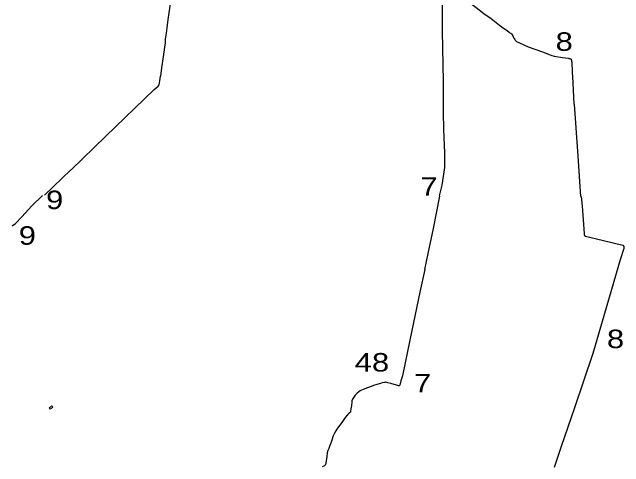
# Model space of a CAD drawing. Extents: x 476989 to 498418, y 4381813 to 4416555.
# Drawn here: x 485779 to 487432, y 4383399 to 4384627 of the extents above; entities that cross this region are included whole.
import ezdxf
from ezdxf.enums import TextEntityAlignment as Align

# ---------------------------------------------------------------- set-up
doc = ezdxf.new("R2010")
doc.units = 0
doc.header["$LTSCALE"] = 20
doc.linetypes.add('MEDIUM_DASHED', pattern=[4.5, 3, -1.5])
for name, color, linetype, lineweight in [('13', 7, 'Continuous', 13), ('48', 7, 'MEDIUM_DASHED', 13), ('6', 7, 'Continuous', 25)]:
    doc.layers.add(name, color=color, linetype=linetype, lineweight=lineweight)

msp = doc.modelspace()

# ---------------------------------------------------------------- linework, layer by layer
at = {"layer": '48'}
msp.add_lwpolyline([(485881.83, 4383554.31), (485889.05, 4383559.53), (485886.53, 4383563.02), (485879.31, 4383557.8)], close=True, dxfattribs=at)
at = {"layer": '6'}
for p, q in [((487294.23, 4384435.36), (487297.15, 4384378.58)), ((485866.75, 4384132.44), (485938.06, 4384200.82)), ((486902.72, 4383974.83), (486893.73, 4383931.56))]:
    msp.add_line(p, q, dxfattribs=at)
for points in [[(486218.38, 4384758.97), (486215.66, 4384730.87), (486211.01, 4384695.06), (486207.54, 4384662.09), (486202.36, 4384625.46), (486200.14, 4384606.58), (486197.13, 4384584.8), (486195.49, 4384569.88), (486192.94, 4384553.94), (486192.12, 4384543.7), (486190.9, 4384532.35), (486188.75, 4384518.64), (486187.3, 4384506.44), (486183.04, 4384476.01), (486180.3, 4384454.17)], [(486945.56, 4384310.48), (486944.94, 4384355.68), (486944.63, 4384415.82), (486944.32, 4384439.71), (486942.16, 4384575.23), (486941.95, 4384690.43)], [(486942.08, 4384690.84), (486954.99, 4384685.27), (486964.75, 4384681.01), (486968.71, 4384679.29), (486972.07, 4384677.74), (486975.6, 4384676.25), (486980.04, 4384673.88), (486984.28, 4384670.81), (486999.05, 4384662.28), (487012.48, 4384653.89), (487024.7, 4384645.52), (487041.38, 4384633.38), (487053.31, 4384623.24), (487073.79, 4384609.31), (487096.07, 4384592.1), (487101.96, 4384587.52)], [(487101.8, 4384587.52), (487116.55, 4384577.26), (487122.3, 4384573.1), (487124.64, 4384571.25), (487125.02, 4384570.92), (487125.52, 4384570.61), (487127.05, 4384569.38), (487128.24, 4384568.15), (487130.32, 4384565.69), (487131.92, 4384562.86), (487133.39, 4384560.05), (487135.2, 4384556.68), (487136.02, 4384555.28), (487137.14, 4384552.89), (487137.22, 4384552.72), (487138.44, 4384551.25), (487140.08, 4384549.42), (487141.78, 4384547.95), (487149.75, 4384543.71), (487173.68, 4384533.05), (487212.25, 4384519.67), (487233.09, 4384511.72), (487237.67, 4384509.96), (487243.84, 4384508.31), (487266.13, 4384504.33), (487282.11, 4384502.38), (487283.68, 4384502.03), (487285.79, 4384501.45), (487287.55, 4384500.79), (487289.12, 4384499.93), (487290.33, 4384497.55), (487290.92, 4384494.24), (487291.11, 4384491.51), (487292.47, 4384465.24), (487294.23, 4384435.67)], [(485938.1, 4384200.87), (486031.09, 4384290.93), (486163.16, 4384417.62), (486173.25, 4384426.84), (486175.9, 4384430.9), (486178.46, 4384441.13), (486180.3, 4384454.17)], [(487297.44, 4384378.01), (487307.43, 4384237.38), (487314.66, 4384129.23)], [(486934.14, 4384130.55), (486940.93, 4384159.51), (486948.64, 4384207.59), (486948.03, 4384246.42), (486946.18, 4384288.58), (486945.56, 4384310.48)], [(485779.25, 4384049.24), (485787.67, 4384056.24), (485804.97, 4384074.17), (485831.97, 4384103.43), (485861.35, 4384131.61)], [(486934.14, 4384129.53), (486916.73, 4384042.26), (486902.62, 4383974.52)], [(487317.13, 4384128.79), (487319.18, 4384102.5), (487324.43, 4384028.76), (487324.46, 4384025.91), (487325.54, 4384023.43), (487328.03, 4384021.89), (487429.49, 4383997.14), (487431.73, 4383993.45), (487431.84, 4383988.48), (487422.32, 4383957.52), (487348.01, 4383704.94), (487298.99, 4383557.78), (487262.98, 4383453.83), (487243.49, 4383397.09)], [(486893.84, 4383931.34), (486880.94, 4383870.04), (486854.54, 4383744.96), (486833.62, 4383644.09)], [(486833.62, 4383644.09), (486829.57, 4383630.55), (486827.02, 4383619.53)], [(486826.89, 4383619.48), (486825.23, 4383617.64), (486823.45, 4383617.32), (486817.23, 4383619.19), (486802.39, 4383623.82), (486794.27, 4383625.68), (486789.22, 4383626.87), (486786.8, 4383626.58), (486784.88, 4383626.6), (486778.78, 4383625.44), (486774.01, 4383623.98), (486758.45, 4383618.79), (486728.02, 4383607.73), (486722.8, 4383605.72), (486719.23, 4383603.45), (486715.99, 4383601.58), (486710.95, 4383597.61), (486705.68, 4383591.8), (486702.17, 4383586.52), (486698.61, 4383581.29), (486697.25, 4383576.87), (486696.73, 4383573.56), (486695.83, 4383564.12), (486694.52, 4383555.26), (486693.37, 4383548.23), (486692.99, 4383545.88), (486689.77, 4383544.13), (486683.85, 4383537.38), (486677.07, 4383528.72), (486669.63, 4383518.52), (486658.36, 4383502.75), (486653.4, 4383495.54), (486650.12, 4383489.18), (486646.74, 4383482.31), (486641.62, 4383467.51), (486636.62, 4383453.34), (486634.83, 4383448.37), (486632.39, 4383442.5), (486630.76, 4383436.09), (486629.41, 4383425.92), (486627.6, 4383415.24), (486626.45, 4383407.65), (486625.31, 4383403), (486623.23, 4383401.09), (486621.01, 4383400.11), (486616.4, 4383398.76)]]:
    msp.add_lwpolyline(points, dxfattribs=at)

# ---------------------------------------------------------------- texts
at = {"layer": '13', "width": 1.25}
for s, p in [('8', (487270.88, 4384522.38)), ('7', (486905.66, 4384130.97))]:
    msp.add_text(s, height=50, dxfattribs=at).set_placement(p, align=Align.CENTER)
for s, p in [('9', (485870.68, 4384094.81)), ('9', (485796.91, 4383998.4)), ('8', (487386.35, 4383719.24)), ('48', (486704.87, 4383655.94)), ('7', (486865.07, 4383599.48))]:
    msp.add_text(s, height=50, dxfattribs=at).set_placement(p)

doc.saveas('drawing.dxf')
